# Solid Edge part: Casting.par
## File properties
Author: Administrator
Template: Normal.par
Last saved by: CADCIM
Revision: 25
Application: Solid Edge
Accuracy: 0.99
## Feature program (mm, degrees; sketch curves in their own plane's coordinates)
pattern "unnamed Pattern 1"
pattern "unnamed Pattern 2"
base feature "unnamed BaseFeature 1"
sketch for "unnamed Cutout 1" plane through (0, -28, 34) normal (0, -1, 0) x-axis (1, 0, 0)
extrude "unnamed Cutout 1" cut
Other named dimensions: "Hole_3": Diameter = 8 mm | "Hole_1": VBottomAngle = 90 deg
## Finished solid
Body 1: solid body, 53 faces, 134 edges, 84 vertices.
  Faces by surface: plane 39, cylinder 10, cone 2, torus 2
  Edges by curve: line 106, circle 23, intersection 5
Bounding box of the edges (mm; curved faces can reach further): 208.027 x 56.000 x 68.000, from (-104.0133, -28, 0) to (104.0133, 28, 68).
Cylindrical faces by radius (mm): R4 x1, R6 x4, R7 x2, R24 x1, R54 x2
Conical faces (half-angle, radius in mm at the cone's reference point): 45 deg R24 x1, 45 deg R26 x1
Toroidal faces (ring radius, tube radius in mm): R62 r8 x2
Planar faces by outward normal: +x 6, +y 6, +z 7, -x 6, -y 6, -z 4, oblique 4
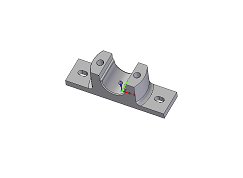
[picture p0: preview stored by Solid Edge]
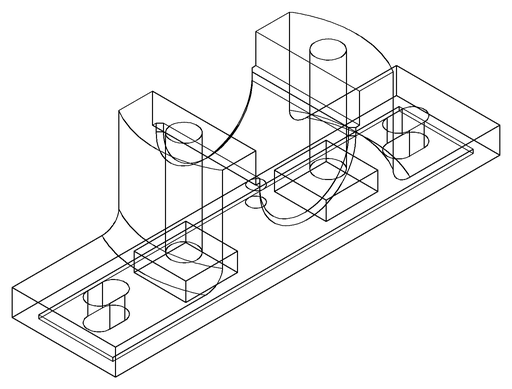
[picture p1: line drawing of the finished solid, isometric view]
